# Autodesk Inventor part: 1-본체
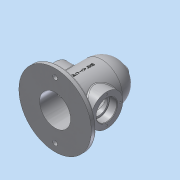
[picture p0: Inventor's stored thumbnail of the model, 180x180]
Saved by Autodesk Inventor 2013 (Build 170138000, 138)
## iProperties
Created: 2019-11
Part Number: 1-본체
Material: 알루미늄 6061
Document SubType Name: Modeling
Designer: Administrator
Density: 2.71 g/cm^3
Mass: 1110.22 g
Surface Area: 883.25 cm^2
Volume: 409.674 cm^3
Author: Administrator
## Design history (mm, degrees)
sketch "스케치1"
  geometry: L1 (0, 0)-(40, 0); L2 (0, 0)-(0, 130); L3 (40, 0)-(40, 90); A1 r 40 centre (0, 90) between (40, 90) and (0, 130)
  constraints: 6 end point, 2 point on circle, 1 centre point, 1 horizontal, 1 perpendicular, 1 tangent, 1 vertical
  dimensions: "d0" = 130 distance of L1.start L2.end; "d1" = 40 distance of L1.start L1.end; "d3" = 40 radius of A1
revolve "회전1" sketch "스케치1" stored, may be unused: angle "d4" = 90 deg
feature "쉘1" dims "d5" = 10
sketch "스케치2"
  geometry: C1 r 40 at (0, 0) reference; C2 r 70 at (0, 0)
  constraints: 1 centre point, 1 coincident
  dimensions: "d6" = 140 diameter of C2
extrude "돌출1" join sketch "스케치2" distance "d8" = 10; taper "d9" = 0 deg
node "작업 평면1"
sketch "스케치3"
  geometry: C1 r 7.5 at (0, 0); 1 further point
  constraints: 1 centre point, 1 coincident
  dimensions: "d11" = 15 diameter of C1
extrude "돌출2" join sketch "스케치3" stored distance "d13" = 10; taper "d14" = 0 deg
node "작업 평면2"
sketch "스케치4"
  geometry: L1 (0, -70)-(0, 70) reference; C1 r 31 at (50, 0); 1 further point
  constraints: 1 centre point, 1 horizontal alignment
  dimensions: "d16" = 62 diameter of C1; "d18" = 50 distance from line of L1 C1.centre
extrude "돌출3" join sketch "스케치4" stored distance "d19" = 10; taper "d20" = 0 deg
sketch "스케치5"
  geometry: C1 r 31 at (0, 0) reference; 2 further points
  constraints: 1 coincident
hole "구멍1" sketch "스케치5" at (0, 0) diameter "d21" = 40; stored, may be unused: countersink angle "d25" = 90 deg, drill point angle "d27" = 0 deg; dims "d22" = 6, "d23" = 4, "d24" = 2, "d26" = 15
sketch "스케치6"
  geometry: C1 r 31 at (0, 0) reference; 2 further points
  constraints: 1 coincident
hole "구멍2" sketch "스케치6" at (0, 0) diameter "d28" = 40; stored, may be unused: countersink angle "d32" = 90 deg, drill point angle "d34" = 0 deg; dims "d29" = 6, "d30" = 4, "d31" = 2, "d33" = 15
sketch "스케치7"
  geometry: C1 r 20 at (0, 0) reference; 2 further points
  constraints: 1 coincident
hole "구멍3" sketch "스케치7" at (0, 0) diameter "d35" = 33; stored, may be unused: countersink angle "d39" = 90 deg, drill point angle "d41" = 0 deg; dims "d36" = 6, "d37" = 4, "d38" = 2, "d40" = 15
sketch "스케치8"
  geometry: C1 r 20 at (0, 0) reference; 2 further points
  constraints: 1 vertical alignment
  dimensions: "d42" = 26 distance of C1.centre point (0, 26)
hole "구멍4" sketch "스케치8" at (0, 26) diameter "d43" = 3.242; stored, may be unused: countersink angle "d47" = 90 deg, drill point angle "d49" = 118 deg; dims "d44" = 8, "d45" = 4, "d46" = 2, "d48" = 10
sketch "스케치9"
  geometry: C1 r 7.5 at (0, 0) reference; 1 further point
  constraints: 1 coincident
hole "구멍5" sketch "스케치9" at (0, 0) diameter "d53" = 5.188; stored, may be unused: countersink angle "d57" = 90 deg, drill point angle "d59" = 118 deg; dims "d54" = 8, "d55" = 4, "d56" = 2, "d58" = 10
node "작업 평면4"
sketch "스케치10"
  geometry: L1 (70, 0)-(-70, 0) reference; 2 further points
  constraints: 1 vertical alignment, 1 other
  dimensions: "d61" = 50 distance from line of L1 point (0, 50)
feature "엠보싱1" sketch "스케치10" dims "d62" = 0.5, "d63" = 0
sketch "스케치11"
  geometry: C1 r 40 at (0, 0) reference; 2 further points
  constraints: 2 vertical alignment
  dimensions: "d64" = 55 distance of C1.centre point (0, 55); "d65" = 110 distance of point (0, -55) point (0, 55)
hole "구멍6" sketch "스케치11" at (0, -55), (0, 55) diameter "d66" = 9; stored, may be unused: countersink angle "d70" = 90 deg, drill point angle "d72" = 118 deg; dims "d67" = 8, "d68" = 4, "d69" = 2, "d71" = 10
fillet "모깎기1" dims "d73" = 0.3
chamfer "모따기1" distance "d74" = 1; stored, may be unused: second distance "d75" = 2, angle "d76" = 45 deg
fillet "모깎기2" dims "d77" = 3
fillet "모깎기3" dims "d78" = 3
fillet "모깎기4" dims "d79" = 3
node "솔리드1"
mirror "대칭1"
pattern_circular "원형 패턴1" dims angle "d51" = 360 deg
mirror "대칭2"
node "작업 평면3"
other parameters: "d10" = 135, "d60" = 55
